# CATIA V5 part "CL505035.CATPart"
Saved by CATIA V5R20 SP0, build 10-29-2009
Part number: CL505035
Bounding box of the stored display mesh (mm): x -17.5 to 17.5, y -13 to 13, z 0 to 41
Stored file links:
  C:\Users\Raffaele\Desktop\3D X SITO CF\BOLEX\17-CENTERER REF 505\CL505035.CATPart
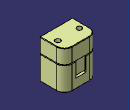
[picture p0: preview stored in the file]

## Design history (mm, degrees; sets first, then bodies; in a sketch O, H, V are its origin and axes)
Set1
  DatumSurface1 to DatumSurface29 "MANIFOLD_SOLID_BREP #858"
  DatumSurface30 to DatumSurface104 "MANIFOLD_SOLID_BREP #2939"
  DatumSurface105 to DatumSurface108 "MANIFOLD_SOLID_BREP #3027"
  DatumSurface109 to DatumSurface112 "MANIFOLD_SOLID_BREP #3115"
  DatumSurface113 to DatumSurface116 "MANIFOLD_SOLID_BREP #3203"
  DatumSurface117 to DatumSurface120 "MANIFOLD_SOLID_BREP #3291"
  DatumSurface121 to DatumSurface124 "MANIFOLD_SOLID_BREP #3379"
  DatumSurface125 to DatumSurface128 "MANIFOLD_SOLID_BREP #3467"
  DatumSurface129 to DatumSurface132 "MANIFOLD_SOLID_BREP #3555"
  DatumSurface133 to DatumSurface136 "MANIFOLD_SOLID_BREP #3643"
  DatumSurface137 to DatumSurface140 "MANIFOLD_SOLID_BREP #3731"
  DatumSurface141 to DatumSurface144 "MANIFOLD_SOLID_BREP #3819"
  DatumSurface145 to DatumSurface148 "MANIFOLD_SOLID_BREP #3907"
  DatumSurface149 to DatumSurface152 "MANIFOLD_SOLID_BREP #3995"
Body1 (main body)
